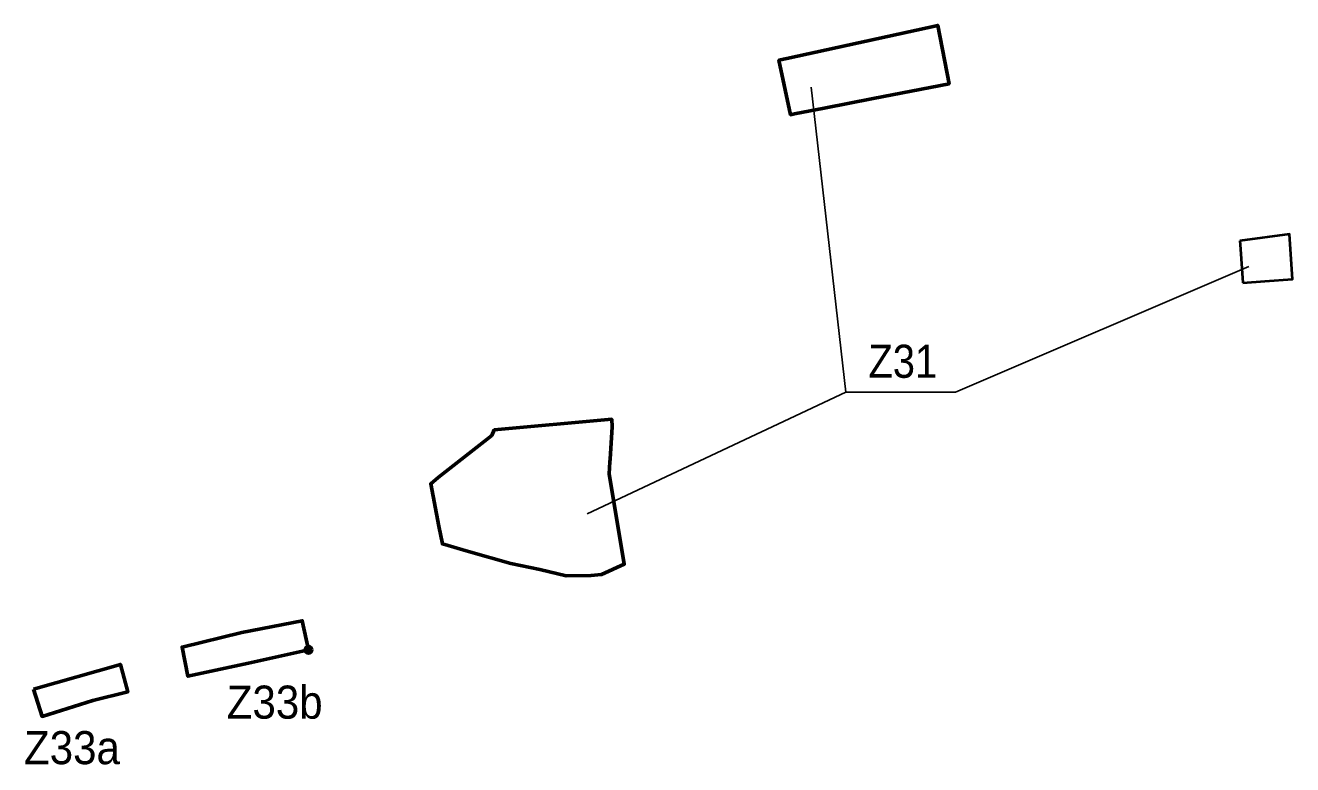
# Model space of a CAD drawing. Extents: x -650277 to -643425, y -1073980 to -1066720.
# Drawn here: x -644344 to -643425, y -1070237 to -1069701 of the extents above; entities that cross this region are included whole.
import ezdxf

# ---------------------------------------------------------------- set-up
doc = ezdxf.new("R2010")
doc.units = 0
doc.header["$LTSCALE"] = 9.6
doc.header["$PDMODE"] = 32
doc.header["$PDSIZE"] = 4.8
for name, color, linetype, lineweight in [('2', 7, 'Continuous', 40), ('3', 7, 'Continuous', 60), ('5', 7, 'Continuous', 60), ('59', 7, 'Continuous', 25), ('63', 7, 'Continuous', 25), ('8', 7, 'Continuous', 60)]:
    doc.layers.add(name, color=color, linetype=linetype, lineweight=lineweight)

msp = doc.modelspace()

# ---------------------------------------------------------------- linework, layer by layer
at = {"layer": '2'}
for points in [[(-643461.327, -1069887.84), (-643445.37, -1069886.7), (-643425.253, -1069885.25), (-643427.6, -1069852.59), (-643463.51, -1069857.44)], [(-643463.51, -1069857.44), (-643463.31, -1069860.18), (-643461.327, -1069887.84)]]:
    msp.add_lwpolyline(points, dxfattribs=at)
at = {"layer": '3'}
for points in [[(-643791.88, -1069725.25), (-643797.75, -1069726.51), (-643789.3, -1069766.05), (-643786.35, -1069765.46), (-643764.94, -1069761.27), (-643729.34, -1069754.3), (-643674.3, -1069743.53), (-643682.61, -1069701.16)], [(-643920.84, -1070026.46), (-643920.29, -1070017.73), (-643920.16, -1070015.69), (-643918.69, -1069992.23), (-643918.88, -1069986.82), (-644004.06, -1069994.59), (-644005.92, -1069998.62), (-644044.7, -1070029.04), (-644050.12, -1070033.64), (-644044.18, -1070064.43), (-644041.71, -1070077.29), (-644022.77, -1070082.66), (-643991.99, -1070091.37), (-643971.03, -1070095.79), (-643951.99, -1070100.35), (-643933.96, -1070100.18), (-643926.33, -1070099.5), (-643909.87, -1070091.95)]]:
    msp.add_lwpolyline(points, close=True, dxfattribs=at)
at = {"layer": '5'}
msp.add_lwpolyline([(-644338.06, -1070182.64), (-644331.9, -1070202.4), (-644295.01, -1070190.9), (-644269.84, -1070184.57), (-644275.05, -1070164.59)], close=True, dxfattribs=at)
at = {"layer": '59'}
msp.add_lwpolyline([(-643457, -1069876), (-643669.749, -1069967.17), (-643749.085, -1069967.17)], dxfattribs=at)
at = {"layer": '63'}
for p, q in [((-643749.085, -1069967.17), (-643774.294, -1069746.101)), ((-643936.672, -1070055.449), (-643749.085, -1069967.17))]:
    msp.add_line(p, q, dxfattribs=at)
at = {"layer": '8'}
for p, q in [((-644138.78, -1070154.07), (-644143.31, -1070132.95)), ((-644182.31, -1070163.66), (-644138.78, -1070154.07))]:
    msp.add_line(p, q, dxfattribs=at)
msp.add_lwpolyline([(-644143.31, -1070132.95), (-644143.31, -1070132.95), (-644143.31, -1070132.95), (-644187.11, -1070141.58), (-644230.4, -1070152.08), (-644226.23, -1070173.28), (-644182.31, -1070163.66)], dxfattribs=at)
msp.add_point((-644138.78, -1070154.07), dxfattribs=at)

# ---------------------------------------------------------------- texts
at = {"layer": '59', "width": 0.9}
msp.add_text('Z31', height=24, dxfattribs=at).set_placement((-643732.773, -1069956.784))
at = {"layer": '63', "width": 0.95}
for s, p in [('Z33b', (-644198, -1070204)), ('Z33a', (-644345, -1070237))]:
    msp.add_text(s, height=24, dxfattribs=at).set_placement(p)

doc.saveas('drawing.dxf')
